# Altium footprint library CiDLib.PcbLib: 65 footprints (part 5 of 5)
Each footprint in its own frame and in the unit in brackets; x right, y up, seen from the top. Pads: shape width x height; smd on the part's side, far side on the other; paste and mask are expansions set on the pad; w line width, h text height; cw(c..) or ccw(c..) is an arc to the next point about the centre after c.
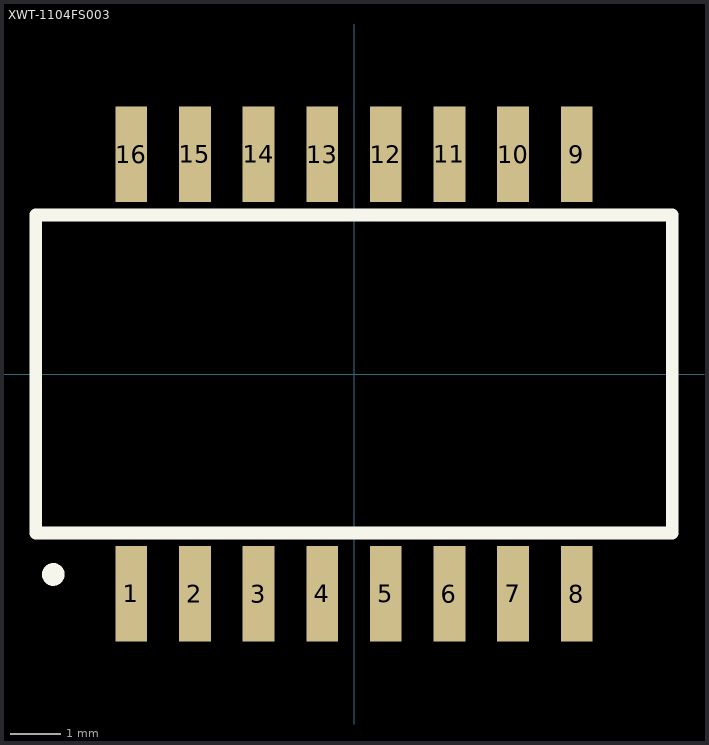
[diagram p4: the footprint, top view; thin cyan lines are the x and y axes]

## XWT-1104FS003 [mil] "XW LAN Transformer"
pads (16):
  rect 25x75 smd: 1(-175,-172.5) 2(-125,-172.5) 3(-75,-172.5) 4(-25,-172.5) 5(25,-172.5) 6(75,-172.5) 7(125,-172.5) 8(175,-172.5) 9(175,172.5) 10(125,172.5) 11(75,172.5) 12(25,172.5) 13(-25,172.5) 14(-75,172.5) 15(-125,172.5) 16(-175,172.5)
Top Overlay:
  circle w10: c-236.22,-157.48 r3.94
  lines w10: -250,-125 -250,125 250,125 250,-125 -250,-125
3D body: height 210, standoff 0, extent -249.98,-124.98 249.98,124.98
